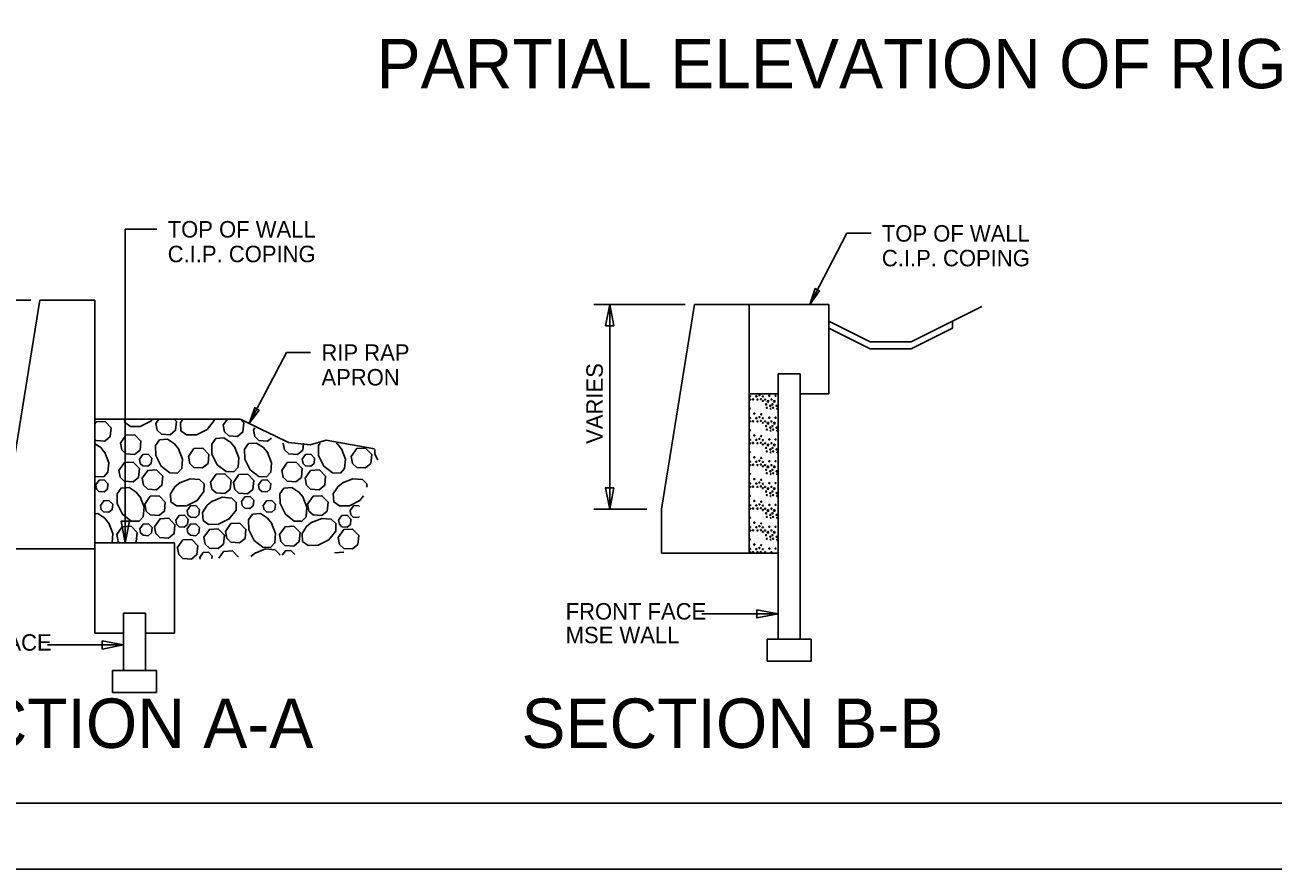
# Model space of a CAD drawing. Extents: x 96 to 240, y 601 to 689.
# Drawn here: x 115.15 to 153.07, y 601 to 626.64 of the extents above; entities that cross this region are included whole.
import ezdxf

# ---------------------------------------------------------------- set-up
doc = ezdxf.new("R2010")
doc.units = 0
for name, color, linetype in [('BR_AUTO DIMENSION', 7, 'Continuous'), ('BR_BORDER LINES', 7, 'Continuous'), ('BR_CONCRETE', 7, 'Continuous'), ('BR_DETAILS', 7, 'Continuous'), ('BR_TEXT', 7, 'Continuous'), ('Level 31', 7, 'Continuous')]:
    doc.layers.add(name, color=color, linetype=linetype)

# ---------------------------------------------------------------- blocks, each defined once
blk = doc.blocks.new('B')
at = {"layer": 'BR_AUTO DIMENSION'}
blk.add_lwpolyline([(-0.2, 0.03), (0, 0), (-0.2, -0.03)], close=True, dxfattribs=at)
blk = doc.blocks.new('ARROW')
at = {"layer": 'BR_AUTO DIMENSION', "xscale": 0.625, "yscale": 0.625}
blk.add_blockref('B', (0, 0), dxfattribs=at)

msp = doc.modelspace()

# ---------------------------------------------------------------- linework, layer by layer
at = {"layer": 'BR_AUTO DIMENSION'}
for p, q in [((118.201, 620.439), (119.163, 620.439)), ((118.201, 610.916), (118.201, 620.439)), ((138.992, 618.156), (140.125, 620.314)), ((140.125, 620.314), (140.856, 620.314)), ((115.328, 618.281), (112.555, 618.281)), ((135.211, 618.156), (132.438, 618.156)), ((132.919, 611.933), (132.919, 618.156)), ((121.969, 614.535), (123.102, 616.693)), ((123.102, 616.693), (123.833, 616.693)), ((134.04, 611.933), (132.438, 611.933)), ((135.718, 608.755), (138.035, 608.755)), ((115.835, 607.809), (118.151, 607.809))]:
    msp.add_line(p, q, dxfattribs=at)
for points in [[(132.794, 617.506), (132.919, 618.156), (133.044, 617.506)], [(133.044, 612.583), (132.919, 611.933), (132.794, 612.583)], [(118.326, 611.566), (118.201, 610.916), (118.076, 611.566)], [(137.385, 608.88), (138.035, 608.755), (137.385, 608.63)], [(117.501, 607.934), (118.151, 607.809), (117.501, 607.684)]]:
    msp.add_lwpolyline(points, close=True, dxfattribs=at)
at = {"layer": 'BR_BORDER LINES'}
msp.add_line((103.173, 603.003), (237.837, 603.003), dxfattribs=at)
at = {"layer": 'BR_CONCRETE'}
for p, q in [((115.608, 618.281), (114.608, 612.058)), ((117.274, 618.281), (115.608, 618.281)), ((117.274, 610.725), (117.274, 618.281)), ((135.491, 618.156), (134.491, 611.933)), ((137.158, 618.156), (135.491, 618.156)), ((137.158, 610.6), (137.158, 618.156)), ((137.158, 618.156), (137.158, 615.437)), ((137.162, 618.156), (139.578, 618.156)), ((139.578, 618.156), (139.578, 615.437)), ((144.222, 618.089), (142.078, 617.017)), ((139.578, 617.642), (140.828, 617.017)), ((143.328, 617.642), (143.328, 617.434)), ((139.578, 617.434), (140.828, 616.809)), ((143.328, 617.434), (142.078, 616.809)), ((140.828, 617.017), (142.078, 617.017)), ((140.828, 616.809), (142.078, 616.809)), ((138.035, 616.041), (138.035, 607.981)), ((138.035, 616.041), (138.701, 616.041)), ((138.701, 616.041), (138.701, 607.981)), ((137.158, 615.437), (138.035, 615.437)), ((139.578, 615.437), (138.701, 615.437)), ((134.491, 611.933), (134.491, 610.6)), ((117.274, 610.916), (119.695, 610.916)), ((117.274, 610.916), (117.274, 608.173)), ((119.695, 610.916), (119.695, 608.173)), ((117.274, 610.725), (114.608, 610.725)), ((137.158, 610.6), (134.491, 610.6)), ((137.158, 610.6), (138.035, 610.6)), ((118.151, 608.777), (118.151, 607.036)), ((118.151, 608.777), (118.818, 608.777)), ((118.818, 608.777), (118.818, 607.036)), ((117.274, 608.173), (118.151, 608.173)), ((119.695, 608.173), (118.818, 608.173)), ((138.035, 607.981), (137.701, 607.981)), ((137.701, 607.981), (137.701, 607.314)), ((138.035, 607.981), (138.701, 607.981)), ((138.701, 607.981), (139.035, 607.981)), ((139.035, 607.981), (139.035, 607.314)), ((118.151, 607.036), (117.818, 607.036)), ((117.818, 607.036), (117.818, 606.369)), ((118.151, 607.036), (118.818, 607.036)), ((118.818, 607.036), (119.151, 607.036)), ((119.151, 607.036), (119.151, 606.369)), ((139.035, 607.314), (137.701, 607.314)), ((119.151, 606.369), (117.818, 606.369))]:
    msp.add_line(p, q, dxfattribs=at)
at = {"layer": 'BR_DETAILS'}
msp.add_line((143.26, 617.4), (143.264, 617.408), dxfattribs=at)
at = {"layer": 'BR_TEXT'}
for p, q in [((117.281, 614.664), (118.364, 614.664)), ((118.364, 614.664), (119.235, 614.664)), ((119.133, 614.54), (119.224, 614.67)), ((119.235, 614.664), (119.703, 614.664)), ((119.703, 614.664), (119.954, 614.664)), ((119.954, 614.664), (121.703, 614.664)), ((121.178, 614.493), (121.302, 614.67)), ((121.703, 614.664), (122.335, 614.359)), ((122.097, 614.347), (122.138, 614.406)), ((122.335, 614.359), (122.746, 614.16)), ((122.746, 614.16), (123.157, 613.961)), ((123.002, 613.94), (123.002, 613.941)), ((123.157, 613.961), (123.817, 613.884)), ((123.817, 613.884), (124.306, 614.032)), ((124.306, 614.032), (124.808, 613.941)), ((124.808, 613.941), (125.773, 613.766)), ((120.479, 610.42), (120.469, 610.471)), ((122.014, 610.492), (122.16, 610.609))]:
    msp.add_line(p, q, dxfattribs=at)
for points in [[(117.274, 614.524), (117.318, 614.586), (117.586, 614.601), (117.773, 614.408), (117.746, 614.137), (117.58, 613.999), (117.315, 614.018), (117.274, 614.058)], [(119.028, 614.67), (118.981, 614.611), (118.659, 614.45), (118.356, 614.444), (118.185, 614.566), (118.178, 614.67)], [(119.689, 614.67), (119.756, 614.601), (119.729, 614.33), (119.563, 614.192), (119.298, 614.212), (119.173, 614.333), (119.133, 614.54)], [(120.898, 614.67), (120.897, 614.623), (120.689, 614.357), (120.367, 614.196), (120.064, 614.19), (119.893, 614.312), (119.877, 614.553), (119.952, 614.67)], [(121.689, 614.67), (121.801, 614.554), (121.774, 614.283), (121.608, 614.146), (121.343, 614.165), (121.218, 614.286), (121.178, 614.493)], [(118.055, 613.94), (118.223, 614.18), (118.491, 614.195), (118.678, 614.001), (118.651, 613.73), (118.485, 613.593), (118.22, 613.612), (118.096, 613.733), (118.055, 613.94)], [(122.641, 614.094), (122.527, 613.999), (122.262, 614.018), (122.137, 614.139), (122.097, 614.347)], [(117.274, 613.924), (117.459, 613.806), (117.585, 613.647)], [(119.819, 613.772), (119.944, 613.457), (119.919, 613.168), (119.788, 613.031), (119.554, 613.036), (119.288, 613.244), (119.127, 613.566), (119.121, 613.869), (119.243, 614.04), (119.485, 614.056), (119.701, 613.918), (119.827, 613.759)], [(121.527, 613.812), (121.652, 613.498), (121.627, 613.209), (121.497, 613.072), (121.262, 613.076), (120.996, 613.285), (120.835, 613.607), (120.83, 613.91), (120.951, 614.081), (121.193, 614.097), (121.409, 613.958), (121.535, 613.8)], [(122.524, 613.66), (122.648, 613.345), (122.624, 613.057), (122.493, 612.919), (122.259, 612.924), (121.992, 613.132), (121.831, 613.454), (121.826, 613.757), (121.947, 613.928), (122.189, 613.944), (122.405, 613.806), (122.532, 613.647)], [(123.619, 613.941), (123.598, 613.73), (123.432, 613.593), (123.167, 613.612), (123.042, 613.733), (123.002, 613.94)], [(124.766, 613.772), (124.891, 613.457), (124.866, 613.168), (124.735, 613.031), (124.501, 613.036), (124.235, 613.244), (124.074, 613.566), (124.068, 613.869), (124.119, 613.941)], [(124.611, 613.941), (124.647, 613.918), (124.774, 613.759)], [(117.577, 613.66), (117.702, 613.345), (117.677, 613.057), (117.546, 612.919), (117.312, 612.924), (117.274, 612.953)], [(118.632, 613.451), (118.733, 613.594), (118.894, 613.603), (119.006, 613.487), (118.99, 613.325), (118.891, 613.242), (118.732, 613.253), (118.657, 613.326), (118.633, 613.451)], [(120.121, 613.534), (120.289, 613.773), (120.558, 613.788), (120.744, 613.595), (120.717, 613.324), (120.551, 613.186), (120.286, 613.205), (120.162, 613.326), (120.121, 613.534)], [(123.579, 613.451), (123.68, 613.594), (123.841, 613.603), (123.953, 613.487), (123.937, 613.325), (123.837, 613.242), (123.678, 613.253), (123.604, 613.326), (123.579, 613.451)], [(125.068, 613.534), (125.236, 613.773), (125.504, 613.788), (125.691, 613.595), (125.664, 613.324), (125.498, 613.186), (125.233, 613.205), (125.109, 613.326), (125.068, 613.534)], [(125.87, 613.431), (125.782, 613.607), (125.779, 613.748)], [(118.008, 613.11), (118.176, 613.349), (118.444, 613.365), (118.631, 613.171), (118.604, 612.9), (118.438, 612.762), (118.173, 612.782), (118.048, 612.902), (118.008, 613.11)], [(118.718, 612.873), (118.886, 613.112), (119.154, 613.127), (119.341, 612.934), (119.314, 612.663), (119.148, 612.525), (118.883, 612.544), (118.759, 612.665), (118.718, 612.873)], [(122.955, 613.11), (123.123, 613.349), (123.391, 613.365), (123.578, 613.171), (123.551, 612.9), (123.385, 612.762), (123.12, 612.782), (122.995, 612.902), (122.955, 613.11)], [(123.665, 612.873), (123.833, 613.112), (124.101, 613.127), (124.288, 612.934), (124.261, 612.663), (124.095, 612.525), (123.83, 612.544), (123.705, 612.665), (123.665, 612.873)], [(117.303, 612.67), (117.404, 612.814), (117.565, 612.823), (117.677, 612.707), (117.661, 612.544), (117.561, 612.462), (117.402, 612.473), (117.327, 612.546), (117.303, 612.67)], [(119.856, 612.733), (120.171, 612.857), (120.46, 612.832), (120.597, 612.702), (120.592, 612.467), (120.384, 612.201), (120.062, 612.04), (119.759, 612.035), (119.588, 612.156), (119.572, 612.398), (119.71, 612.614), (119.869, 612.741)], [(120.794, 612.754), (120.962, 612.994), (121.23, 613.009), (121.417, 612.815), (121.39, 612.544), (121.224, 612.407), (120.959, 612.426), (120.834, 612.547), (120.794, 612.754)], [(121.485, 612.744), (121.653, 612.983), (121.922, 612.999), (122.108, 612.805), (122.081, 612.534), (121.915, 612.396), (121.65, 612.416), (121.526, 612.536), (121.485, 612.744)], [(122.25, 612.67), (122.351, 612.814), (122.512, 612.823), (122.624, 612.707), (122.607, 612.544), (122.508, 612.462), (122.349, 612.473), (122.274, 612.546), (122.25, 612.67)], [(125.441, 612.342), (125.331, 612.201), (125.009, 612.04), (124.705, 612.035), (124.535, 612.156), (124.518, 612.398), (124.657, 612.614), (124.816, 612.741)], [(124.803, 612.733), (125.117, 612.857), (125.406, 612.832), (125.544, 612.702), (125.542, 612.598)], [(118.65, 612.308), (118.775, 611.993), (118.75, 611.704), (118.619, 611.567), (118.385, 611.571), (118.118, 611.78), (117.958, 612.102), (117.952, 612.405), (118.074, 612.576), (118.315, 612.592), (118.531, 612.454), (118.658, 612.295)], [(118.793, 612.086), (118.961, 612.325), (119.229, 612.341), (119.416, 612.147), (119.389, 611.876), (119.223, 611.738), (118.958, 611.758), (118.833, 611.878), (118.793, 612.086)], [(120.832, 612.171), (121.146, 612.296), (121.435, 612.271), (121.572, 612.14), (121.568, 611.906), (121.36, 611.639), (121.038, 611.478), (120.734, 611.473), (120.563, 611.594), (120.547, 611.836), (120.686, 612.052), (120.844, 612.179)], [(121.73, 612.166), (121.831, 612.309), (121.992, 612.319), (122.103, 612.203), (122.087, 612.04), (121.988, 611.957), (121.829, 611.969), (121.754, 612.041), (121.73, 612.166)], [(123.597, 612.308), (123.721, 611.993), (123.696, 611.704), (123.566, 611.567), (123.332, 611.571), (123.065, 611.78), (122.904, 612.102), (122.899, 612.405), (123.02, 612.576), (123.262, 612.592), (123.478, 612.454), (123.605, 612.295)], [(123.74, 612.086), (123.908, 612.325), (124.176, 612.341), (124.363, 612.147), (124.336, 611.876), (124.17, 611.738), (123.905, 611.758), (123.78, 611.878), (123.74, 612.086)], [(117.445, 612.048), (117.546, 612.191), (117.707, 612.2), (117.819, 612.084), (117.803, 611.922), (117.703, 611.839), (117.544, 611.851), (117.469, 611.923), (117.445, 612.048)], [(120.083, 611.89), (120.183, 612.034), (120.344, 612.043), (120.456, 611.927), (120.44, 611.764), (120.341, 611.681), (120.182, 611.693), (120.107, 611.765), (120.083, 611.89)], [(122.392, 612.048), (122.493, 612.191), (122.654, 612.2), (122.766, 612.084), (122.749, 611.922), (122.65, 611.839), (122.491, 611.851), (122.416, 611.923), (122.392, 612.048)], [(125.029, 611.89), (125.13, 612.034), (125.291, 612.043), (125.318, 612.015)], [(117.274, 611.793), (117.364, 611.799), (117.58, 611.661), (117.707, 611.502)], [(119.089, 611.402), (119.257, 611.641), (119.525, 611.657), (119.712, 611.463), (119.685, 611.192), (119.519, 611.054), (119.254, 611.074), (119.129, 611.194), (119.089, 611.402)], [(119.736, 611.599), (119.837, 611.742), (119.998, 611.751), (120.11, 611.635), (120.093, 611.473), (119.994, 611.39), (119.835, 611.401), (119.76, 611.474), (119.736, 611.599)], [(122.646, 611.514), (122.77, 611.2), (122.745, 610.911), (122.615, 610.774), (122.381, 610.778), (122.114, 610.987), (121.953, 611.309), (121.948, 611.612), (122.069, 611.783), (122.311, 611.799), (122.527, 611.661), (122.654, 611.502)], [(123.857, 611.53), (124.172, 611.655), (124.46, 611.63), (124.598, 611.5), (124.593, 611.265), (124.385, 610.999), (124.063, 610.838), (123.759, 610.833), (123.589, 610.954), (123.572, 611.196), (123.711, 611.412), (123.87, 611.538)], [(124.683, 611.599), (124.783, 611.742), (124.944, 611.751), (125.056, 611.635), (125.04, 611.473), (124.941, 611.39), (124.782, 611.401), (124.707, 611.474), (124.683, 611.599)], [(125.318, 611.707), (125.287, 611.681), (125.128, 611.693), (125.054, 611.765), (125.029, 611.89)], [(117.699, 611.514), (117.824, 611.2), (117.799, 610.916)], [(117.941, 611.162), (118.109, 611.401), (118.378, 611.416), (118.564, 611.223), (118.537, 610.952), (118.493, 610.916)], [(118.021, 610.916), (117.982, 610.954), (117.941, 611.162)], [(118.643, 611.337), (118.744, 611.48), (118.905, 611.489), (119.017, 611.373), (119.001, 611.211), (118.902, 611.128), (118.743, 611.14), (118.668, 611.212), (118.644, 611.337)], [(120.083, 611.337), (120.183, 611.48), (120.344, 611.489), (120.456, 611.373), (120.44, 611.211), (120.341, 611.128), (120.182, 611.14), (120.107, 611.212), (120.083, 611.337)], [(120.592, 611.083), (120.76, 611.322), (121.028, 611.337), (121.215, 611.144), (121.188, 610.873), (121.022, 610.735), (120.757, 610.754), (120.632, 610.875), (120.592, 611.083)], [(121.244, 611.258), (121.412, 611.497), (121.68, 611.513), (121.867, 611.319), (121.84, 611.048), (121.674, 610.91), (121.409, 610.93), (121.284, 611.051), (121.244, 611.258)], [(122.888, 611.162), (123.056, 611.401), (123.324, 611.416), (123.511, 611.223), (123.484, 610.952), (123.318, 610.814), (123.053, 610.833), (122.928, 610.954), (122.888, 611.162)], [(124.671, 611.073), (124.839, 611.312), (125.108, 611.328), (125.294, 611.134), (125.267, 610.863), (125.102, 610.725), (124.837, 610.744), (124.712, 610.865), (124.672, 611.073)], [(119.783, 610.764), (119.952, 611.003), (120.22, 611.018), (120.406, 610.825), (120.379, 610.554), (120.214, 610.416), (119.949, 610.435), (119.824, 610.556), (119.784, 610.764)], [(120.469, 610.471), (120.57, 610.615), (120.731, 610.624), (120.843, 610.508), (120.835, 610.437)], [(121.046, 610.447), (121.188, 610.649), (121.456, 610.664), (121.639, 610.474)], [(122.147, 610.601), (122.462, 610.725), (122.751, 610.7), (122.888, 610.57), (122.887, 610.533)], [(122.972, 610.537), (123.065, 610.67), (123.226, 610.679), (123.338, 610.563), (123.337, 610.554)], [(124.563, 610.611), (124.564, 610.612), (124.832, 610.628), (124.836, 610.624)]]:
    msp.add_lwpolyline(points, dxfattribs=at)
for centre, radius in [((137.178, 615.364), 0.0162), ((137.371, 615.362), 0.0162), ((137.465, 615.394), 0.0162), ((137.572, 615.358), 0.0162), ((137.765, 615.377), 0.0162), ((137.956, 615.377), 0.0162), ((137.174, 614.991), 0.0162), ((137.178, 615.262), 0.0162), ((137.269, 615.269), 0.0162), ((137.407, 615.262), 0.0162), ((137.51, 615.278), 0.0162), ((137.571, 615.223), 0.0162), ((137.638, 615.262), 0.0162), ((137.67, 615.12), 0.0162), ((137.691, 615.014), 0.0162), ((137.725, 615.208), 0.0243), ((137.797, 615.074), 0.0162), ((137.83, 615.262), 0.0162), ((137.862, 615.12), 0.0162), ((137.883, 615.014), 0.0162), ((137.916, 615.208), 0.0243), ((137.989, 615.074), 0.0162), ((137.178, 614.702), 0.0162), ((137.178, 614.6), 0.0162), ((137.269, 614.606), 0.0162), ((137.311, 614.837), 0.0162), ((137.371, 614.699), 0.0162), ((137.407, 614.6), 0.0162), ((137.465, 614.731), 0.0162), ((137.51, 614.616), 0.0162), ((137.52, 614.814), 0.0162), ((137.572, 614.695), 0.0162), ((137.571, 614.56), 0.0162), ((137.638, 614.6), 0.0162), ((137.725, 614.545), 0.0243), ((137.765, 614.714), 0.0162), ((137.83, 614.6), 0.0162), ((137.916, 614.545), 0.0243), ((137.956, 614.714), 0.0162), ((137.174, 614.328), 0.0162), ((137.311, 614.175), 0.0162), ((137.67, 614.458), 0.0162), ((137.691, 614.351), 0.0162), ((137.797, 614.411), 0.0162), ((137.862, 614.458), 0.0162), ((137.883, 614.351), 0.0162), ((137.989, 614.411), 0.0162), ((137.178, 614.039), 0.0162), ((137.178, 613.937), 0.0162), ((137.269, 613.944), 0.0162), ((137.371, 614.037), 0.0162), ((137.407, 613.937), 0.0162), ((137.465, 614.068), 0.0162), ((137.51, 613.953), 0.0162), ((137.52, 614.152), 0.0162), ((137.572, 614.032), 0.0162), ((137.571, 613.898), 0.0162), ((137.638, 613.937), 0.0162), ((137.67, 613.795), 0.0162), ((137.725, 613.883), 0.0243), ((137.765, 614.052), 0.0162), ((137.83, 613.937), 0.0162), ((137.862, 613.795), 0.0162), ((137.916, 613.883), 0.0243), ((137.956, 614.052), 0.0162), ((137.174, 613.665), 0.0162), ((137.311, 613.512), 0.0162), ((137.465, 613.406), 0.0162), ((137.52, 613.489), 0.0162), ((137.691, 613.688), 0.0162), ((137.797, 613.748), 0.0162), ((137.883, 613.688), 0.0162), ((137.989, 613.748), 0.0162), ((137.178, 613.376), 0.0162), ((137.178, 613.274), 0.0162), ((137.269, 613.281), 0.0162), ((137.371, 613.374), 0.0162), ((137.407, 613.274), 0.0162), ((137.51, 613.29), 0.0162), ((137.572, 613.369), 0.0162), ((137.571, 613.235), 0.0162), ((137.638, 613.274), 0.0162), ((137.67, 613.132), 0.0162), ((137.691, 613.025), 0.0162), ((137.725, 613.22), 0.0243), ((137.765, 613.389), 0.0162), ((137.797, 613.085), 0.0162), ((137.83, 613.274), 0.0162), ((137.862, 613.132), 0.0162), ((137.883, 613.025), 0.0162), ((137.916, 613.22), 0.0243), ((137.956, 613.389), 0.0162), ((137.989, 613.085), 0.0162), ((137.174, 613.002), 0.0162), ((137.178, 612.714), 0.0162), ((137.311, 612.849), 0.0162), ((137.371, 612.711), 0.0162), ((137.465, 612.743), 0.0162), ((137.52, 612.826), 0.0162), ((137.572, 612.707), 0.0162), ((137.765, 612.726), 0.0162), ((137.956, 612.726), 0.0162), ((137.174, 612.34), 0.0162), ((137.178, 612.611), 0.0162), ((137.269, 612.618), 0.0162), ((137.407, 612.611), 0.0162), ((137.51, 612.627), 0.0162), ((137.571, 612.572), 0.0162), ((137.638, 612.611), 0.0162), ((137.67, 612.47), 0.0162), ((137.691, 612.363), 0.0162), ((137.725, 612.557), 0.0243), ((137.797, 612.423), 0.0162), ((137.83, 612.611), 0.0162), ((137.862, 612.47), 0.0162), ((137.883, 612.363), 0.0162), ((137.916, 612.557), 0.0243), ((137.989, 612.423), 0.0162), ((137.178, 612.051), 0.0162), ((137.178, 611.949), 0.0162), ((137.269, 611.955), 0.0162), ((137.311, 612.186), 0.0162), ((137.371, 612.048), 0.0162), ((137.407, 611.949), 0.0162), ((137.465, 612.08), 0.0162), ((137.51, 611.965), 0.0162), ((137.52, 612.163), 0.0162), ((137.572, 612.044), 0.0162), ((137.571, 611.909), 0.0162), ((137.638, 611.949), 0.0162), ((137.725, 611.894), 0.0243), ((137.765, 612.064), 0.0162), ((137.83, 611.949), 0.0162), ((137.916, 611.894), 0.0243), ((137.956, 612.064), 0.0162), ((137.174, 611.677), 0.0162), ((137.311, 611.524), 0.0162), ((137.67, 611.807), 0.0162), ((137.691, 611.7), 0.0162), ((137.797, 611.76), 0.0162), ((137.862, 611.807), 0.0162), ((137.883, 611.7), 0.0162), ((137.989, 611.76), 0.0162), ((137.178, 611.388), 0.0162), ((137.178, 611.286), 0.0162), ((137.269, 611.293), 0.0162), ((137.371, 611.386), 0.0162), ((137.407, 611.286), 0.0162), ((137.465, 611.417), 0.0162), ((137.51, 611.302), 0.0162), ((137.52, 611.501), 0.0162), ((137.572, 611.381), 0.0162), ((137.571, 611.247), 0.0162), ((137.638, 611.286), 0.0162), ((137.67, 611.144), 0.0162), ((137.725, 611.232), 0.0243), ((137.765, 611.401), 0.0162), ((137.83, 611.286), 0.0162), ((137.862, 611.144), 0.0162), ((137.916, 611.232), 0.0243), ((137.956, 611.401), 0.0162), ((137.174, 611.014), 0.0162), ((137.311, 610.861), 0.0162), ((137.465, 610.755), 0.0162), ((137.52, 610.838), 0.0162), ((137.691, 611.037), 0.0162), ((137.797, 611.097), 0.0162), ((137.883, 611.037), 0.0162), ((137.989, 611.097), 0.0162), ((137.178, 610.725), 0.0162), ((137.178, 610.623), 0.0162), ((137.269, 610.63), 0.0162), ((137.371, 610.723), 0.0162), ((137.407, 610.623), 0.0162), ((137.51, 610.639), 0.0162), ((137.572, 610.718), 0.0162), ((137.638, 610.623), 0.0162), ((137.765, 610.738), 0.0162), ((137.83, 610.623), 0.0162), ((137.956, 610.738), 0.0162)]:
    msp.add_circle(centre, radius, dxfattribs=at)
for centre, start, end in [((137.815, 614.985), 54.7368, 305.2632), ((138.006, 614.985), 54.7368, 305.2632), ((137.815, 614.322), 54.7368, 305.2632), ((138.006, 614.322), 54.7368, 305.2632), ((137.815, 613.659), 54.7368, 305.2632), ((138.006, 613.659), 54.7368, 305.2632), ((137.815, 612.997), 54.7368, 305.2632), ((138.006, 612.997), 54.7368, 305.2632), ((137.815, 612.334), 54.7368, 305.2632), ((138.006, 612.334), 54.7368, 305.2632), ((137.815, 611.671), 54.7368, 305.2632), ((138.006, 611.671), 54.7368, 305.2632), ((137.815, 611.008), 54.7368, 305.2632), ((138.006, 611.008), 54.7368, 305.2632), ((137.571, 610.584), 89.6323, 90.3677)]:
    msp.add_arc(centre, 0.0162, start, end, dxfattribs=at)
at = {"layer": 'Level 31'}
msp.add_lwpolyline([(95.84, 601.004), (239.84, 601.004), (239.84, 689.004), (95.84, 689.004)], close=True, dxfattribs=at)

# ---------------------------------------------------------------- block references
at = {"layer": 'BR_TEXT', "xscale": 4.000000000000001, "yscale": 3.999999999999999, "rotation": -117.69914388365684}
for p in [(138.993, 618.156), (121.97, 614.536)]:
    msp.add_blockref('ARROW', p, dxfattribs=at)

# ---------------------------------------------------------------- texts
at = {"layer": 'BR_AUTO DIMENSION'}
msp.add_text('VARIES', height=0.5, rotation=90, dxfattribs=at).set_placement((132.708, 613.917))
for s, p in [('FRONT FACE', (131.579, 608.582)), ('FRONT FACE', (111.695, 607.637)), ('MSE WALL', (131.579, 607.861))]:
    msp.add_text(s, height=0.5, dxfattribs=at).set_placement(p)
at = {"layer": 'BR_TEXT'}
for s, height, p in [('PARTIAL ELEVATION OF RIGID BARRIER', 1.5, (125.836, 624.719)), ('TOP OF WALL', 0.5, (119.49, 620.186)), ('TOP OF WALL', 0.5, (141.184, 620.061)), ('C.I.P. COPING', 0.5, (119.49, 619.436)), ('C.I.P. COPING', 0.5, (141.184, 619.311)), ('RIP RAP', 0.5, (124.161, 616.441)), ('APRON', 0.5, (124.161, 615.691)), ('SECTION A-A', 1.5, (111.098, 604.683)), ('SECTION B-B', 1.5, (130.236, 604.683))]:
    msp.add_text(s, height=height, dxfattribs=at).set_placement(p)

doc.saveas('drawing.dxf')
